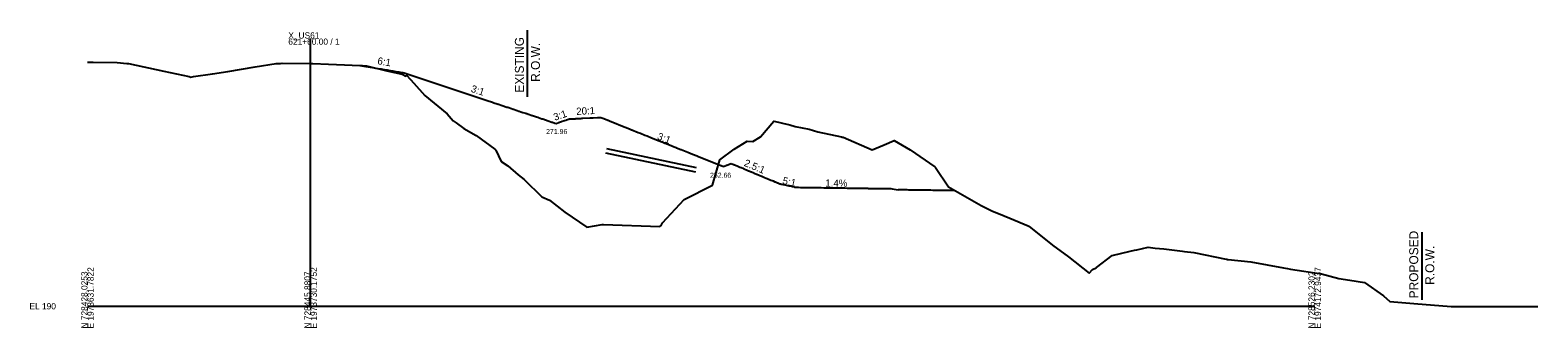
# Model space of a CAD drawing. Extents: x -26 to 1629, y -25 to 9635.
# Drawn here: x -26 to 650, y 3990 to 4124 of the extents above; entities that cross this region are included whole.
import ezdxf

# ---------------------------------------------------------------- set-up
doc = ezdxf.new("R2010")
doc.units = 0
for name, color, linetype in [('Default', 7, 'Continuous'), ('Draft_XS_Grid', 7, 'Continuous'), ('DTM CONTOURS_MAJOR', 7, 'Continuous'), ('DTM_X_GROUND', 7, 'Continuous'), ('XS_CELL', 7, 'Continuous'), ('XS_P_DRAINAGE', 7, 'Continuous'), ('XS_P_GROUND', 7, 'Continuous'), ('XS_P_ROW', 7, 'Continuous'), ('XS_P_TX_DCH', 7, 'Continuous'), ('XS_P_TX_FS_BS', 7, 'Continuous'), ('XS_X_ROW', 7, 'Continuous')]:
    doc.layers.add(name, color=color, linetype=linetype)

msp = doc.modelspace()

# ---------------------------------------------------------------- linework, layer by layer
at = {"layer": 'DTM_X_GROUND'}
msp.add_lwpolyline([(0, 4109.46), (2.62, 4109.41), (13.29, 4109.19), (17.62, 4108.81), (18.34, 4108.75), (34.25, 4105.36), (45.61, 4102.95), (46.39, 4102.76), (47.51, 4102.94), (56.02, 4104.25), (62.92, 4105.3), (75.1, 4107.28), (84.49, 4108.78), (86.52, 4108.86), (87.19, 4108.89), (99.89, 4108.85), (100.95, 4108.84), (108.01, 4108.54), (115.16, 4108.24), (122.13, 4107.95), (123.25, 4107.86), (125.02, 4107.71), (134.18, 4105.55), (141.02, 4103.98), (142.73, 4103.15), (143.07, 4103.49), (146.27, 4100.06), (151.17, 4094.5), (161.13, 4086.23), (163.95, 4083.12), (165.26, 4082.2), (168.72, 4079.69), (174.17, 4076.57), (182.55, 4070.44), (183.05, 4070.01), (185.37, 4064.86), (188.35, 4062.95), (193.06, 4058.86), (195.69, 4056.78), (203.58, 4048.99), (207, 4047.56), (213.96, 4042.24), (223.75, 4035.43), (230.61, 4036.58), (231.17, 4036.66), (231.29, 4036.64), (256.44, 4035.81), (257.08, 4036.15), (257.66, 4037.39), (267.43, 4047.85), (280.06, 4054.29), (283.33, 4065.69), (289.85, 4070.43), (295.59, 4073.96), (298.17, 4073.78), (301.65, 4075.89), (307.58, 4082.92), (309.64, 4082.44), (311.48, 4082.03), (314.83, 4081.26), (317.1, 4080.63), (323.4, 4079.33), (327.36, 4078.21), (337.86, 4076.01), (338.26, 4075.86), (338.47, 4075.79), (338.64, 4075.73), (351.69, 4070.11), (357.03, 4072.36), (361.46, 4074.24), (368.65, 4070.07), (379.82, 4062.47), (380.09, 4062.15), (385.81, 4053.5), (400.47, 4045.14), (403.76, 4043.54), (405.25, 4042.82), (410.88, 4040.5), (413.31, 4039.49), (421.54, 4036.02), (421.71, 4035.95), (421.85, 4035.85), (432.43, 4027.37), (439.61, 4022.07), (448.85, 4014.81), (450.42, 4016.41), (451.99, 4017.28), (452.19, 4017.36), (459.28, 4022.76), (467.33, 4024.62), (469.18, 4025.16), (470.33, 4025.29), (475.33, 4026.47), (478.49, 4026.04), (482.41, 4025.67), (490.78, 4024.72), (491.65, 4024.6), (495.86, 4024.04), (510.33, 4021.08), (510.68, 4021.03), (510.91, 4020.99), (511.25, 4020.94), (521.4, 4019.95), (536.06, 4017.2), (537.8, 4016.95), (539.17, 4016.68), (553, 4014.59), (560.79, 4012.36), (565.77, 4011.69), (572.25, 4010.63), (580.88, 4004.6), (583.61, 4002.06), (596.27, 4001.12), (609.32, 4000), (611.14, 3999.89), (612.47, 3999.89), (614.22, 3999.88), (630.74, 3999.85), (638.79, 3999.94), (650, 3999.93)], dxfattribs=at)
at = {"layer": 'XS_CELL'}
for p, q in [((100, 4000), (100, 4120)), ((0, 4000), (100, 4000)), ((100, 4000), (550, 4000))]:
    msp.add_line(p, q, dxfattribs=at)
at = {"layer": 'XS_P_DRAINAGE'}
for p, q in [((232.15, 4068.7), (272.44, 4060.26)), ((232.56, 4070.65), (272.85, 4062.22))]:
    msp.add_line(p, q, dxfattribs=at)
at = {"layer": 'XS_P_GROUND'}
for points in [[(122, 4107.96), (124.77, 4107.49), (127.71, 4107), (129.02, 4106.79), (130.33, 4106.57), (131.65, 4106.35), (132.96, 4106.13), (134.27, 4105.91), (135.58, 4105.69), (136.89, 4105.47), (138.21, 4105.26), (139.52, 4105.04), (140.17, 4104.93), (140.69, 4104.84), (141.37, 4104.73), (142, 4104.62)], [(142, 4104.62), (145.03, 4103.61), (145.13, 4103.58), (178.74, 4092.38), (179.55, 4092.11), (179.56, 4092.1), (179.97, 4091.97), (180.01, 4091.95), (181.62, 4091.42), (181.68, 4091.4), (184.11, 4090.59), (184.15, 4090.57), (185.78, 4090.03), (185.84, 4090.01), (187.98, 4089.3), (187.99, 4089.29), (188.3, 4089.19), (188.34, 4089.18), (189.99, 4088.63), (190.01, 4088.62), (190.84, 4088.34), (190.88, 4088.33), (192.54, 4087.78), (192.56, 4087.77), (193.39, 4087.49), (193.41, 4087.49), (194.25, 4087.21), (194.27, 4087.2), (195.1, 4086.92), (195.14, 4086.91), (196.4, 4086.49), (196.52, 4086.45), (196.83, 4086.35), (197.42, 4086.15), (197.7, 4086.06), (199.25, 4085.54), (199.45, 4085.47), (199.93, 4085.31), (200.8, 4085.02), (200.82, 4085.02), (200.82, 4085.02), (201.21, 4084.89), (201.83, 4084.68), (202.09, 4084.59), (203.66, 4084.07), (203.85, 4084), (203.96, 4083.97), (204, 4083.96), (206.52, 4083.12), (206.52, 4083.12), (206.52, 4083.12), (208.14, 4082.57), (208.29, 4082.52), (208.31, 4082.52), (208.39, 4082.49), (209.51, 4082.12), (210, 4081.96), (210.82, 4082.23), (211.01, 4082.29), (211.34, 4082.4), (211.54, 4082.47), (212.45, 4082.77), (212.57, 4082.81), (212.81, 4082.89), (213.79, 4083.22), (214.48, 4083.45), (214.63, 4083.5), (214.64, 4083.5), (215.59, 4083.82), (215.68, 4083.85), (216, 4083.96), (216.34, 4083.97), (216.45, 4083.98), (217.2, 4084.02), (217.37, 4084.02), (218.55, 4084.08), (218.85, 4084.1), (219.84, 4084.15), (219.92, 4084.15), (220.85, 4084.2), (221, 4084.21), (221.05, 4084.21), (221.17, 4084.21), (221.59, 4084.24), (221.89, 4084.25), (221.98, 4084.26), (225.12, 4084.41), (225.7, 4084.44), (226.6, 4084.49), (226.64, 4084.49), (226.68, 4084.49), (228.52, 4084.58), (228.54, 4084.58), (229.46, 4084.63), (229.52, 4084.63), (230, 4084.66), (231.35, 4084.12), (231.4, 4084.1), (233.25, 4083.35), (233.28, 4083.35), (234.21, 4082.97), (234.25, 4082.95), (236.12, 4082.21), (236.19, 4082.18), (239.01, 4081.05), (239.06, 4081.03), (240.95, 4080.28), (240.99, 4080.26), (242.89, 4079.5), (242.92, 4079.49), (243.87, 4079.11), (243.94, 4079.08), (246.81, 4077.93), (246.83, 4077.92), (247.8, 4077.54), (247.84, 4077.52), (249.77, 4076.75), (249.8, 4076.74), (250.77, 4076.35), (250.81, 4076.33), (252.76, 4075.55), (252.81, 4075.53), (254.76, 4074.75), (254.78, 4074.74), (255.76, 4074.35), (255.81, 4074.33), (257.78, 4073.55), (257.8, 4073.54), (258.79, 4073.14), (258.84, 4073.12), (260.82, 4072.33), (260.87, 4072.31), (262.86, 4071.51), (262.88, 4071.5), (263.88, 4071.1), (263.93, 4071.08), (265.94, 4070.28), (266.01, 4070.25), (269.04, 4069.04), (269.09, 4069.02), (271.12, 4068.21), (271.17, 4068.19), (273.21, 4067.37), (273.4, 4067.29), (279, 4065.06), (279.06, 4065.03), (283.79, 4063.14), (283.92, 4063.09), (285, 4062.66), (285.17, 4062.72), (285.41, 4062.82), (285.86, 4063), (285.94, 4063.03), (286.08, 4063.09), (286.11, 4063.1), (286.44, 4063.23), (286.48, 4063.25), (288.41, 4064.02)], [(288.41, 4064.02), (289.49, 4063.57), (289.73, 4063.47), (290.65, 4063.09), (291.09, 4062.91), (291.8, 4062.61), (292.4, 4062.36), (292.96, 4062.12), (293.69, 4061.82), (294.12, 4061.64), (294.95, 4061.29), (295.28, 4061.16), (296.2, 4060.77), (296.43, 4060.67), (297.42, 4060.26), (297.59, 4060.19), (298.64, 4059.75), (298.75, 4059.71), (299.86, 4059.24), (299.91, 4059.22), (301.01, 4058.76), (301.06, 4058.74), (301.06, 4058.74), (302.1, 4058.31), (302.22, 4058.26), (303.13, 4057.88), (303.38, 4057.77), (304.17, 4057.44), (304.54, 4057.29), (305.21, 4057.01), (305.7, 4056.81), (306.24, 4056.58), (306.85, 4056.32), (307.28, 4056.15), (308.01, 4055.84), (308.32, 4055.71), (309.17, 4055.36), (309.35, 4055.28), (310.33, 4054.87), (310.39, 4054.85), (310.94, 4054.62)], [(316.89, 4053.33), (316.11, 4053.5), (315.93, 4053.54), (314.96, 4053.75), (314.49, 4053.85), (313.8, 4054), (313.33, 4054.1), (312.64, 4054.25), (311.62, 4054.47), (311.48, 4054.5), (310.94, 4054.62)], [(316.89, 4053.33), (317.27, 4053.33), (317.32, 4053.33), (318.43, 4053.31), (318.63, 4053.31), (319.59, 4053.29), (319.94, 4053.29), (320.74, 4053.28), (321.25, 4053.27), (321.9, 4053.26), (322.56, 4053.25), (323.06, 4053.24), (323.87, 4053.23), (324.22, 4053.23), (325.18, 4053.21), (325.37, 4053.21), (326.49, 4053.19), (326.53, 4053.19), (326.82, 4053.19), (327.69, 4053.18), (327.7, 4053.18), (328.85, 4053.16), (328.88, 4053.16), (330.01, 4053.14), (330.06, 4053.14), (331.16, 4053.13), (331.23, 4053.13), (332.32, 4053.11), (332.41, 4053.11), (333.48, 4053.09), (333.59, 4053.09), (334.64, 4053.08), (334.76, 4053.08), (335.79, 4053.06), (335.94, 4053.06), (336.95, 4053.04), (337.12, 4053.04), (338.11, 4053.03), (338.29, 4053.02), (339.27, 4053.01), (339.47, 4053.01), (340.42, 4052.99), (340.65, 4052.99), (341.58, 4052.98), (341.83, 4052.97), (342.74, 4052.96), (343, 4052.96), (343.9, 4052.94), (344.18, 4052.94), (345.05, 4052.93), (345.36, 4052.92), (346.21, 4052.91), (346.54, 4052.9), (347.37, 4052.89), (347.72, 4052.89), (348.53, 4052.88), (348.9, 4052.87), (349.68, 4052.86), (350.08, 4052.85), (350.84, 4052.84), (351.26, 4052.84), (352, 4052.83), (352.44, 4052.82), (353.16, 4052.81), (353.62, 4052.8), (354.31, 4052.79), (354.8, 4052.79), (355.47, 4052.78), (355.98, 4052.77), (356.63, 4052.76), (357.16, 4052.75), (357.79, 4052.74), (358.34, 4052.73), (358.95, 4052.73), (359.52, 4052.72), (360.1, 4052.71), (360.7, 4052.7), (363.28, 4052.17), (363.28, 4052.17), (363.28, 4052.17), (363.28, 4052.17), (363.28, 4052.17)], [(388.79, 4051.8), (388.17, 4051.81), (388.16, 4051.81), (387.01, 4051.83), (386.98, 4051.83), (385.86, 4051.84), (385.79, 4051.85), (384.7, 4051.86), (384.57, 4051.86), (383.54, 4051.88), (383.35, 4051.88), (382.38, 4051.89), (382.18, 4051.9), (381.22, 4051.91), (381, 4051.91), (380.07, 4051.93), (379.16, 4051.94), (378.91, 4051.95), (378.02, 4051.96), (377.75, 4051.96), (376.87, 4051.97), (376.59, 4051.98), (375.73, 4051.99), (375.44, 4052), (374.59, 4052.01), (374.28, 4052.01), (373.45, 4052.02), (373.12, 4052.03), (372.31, 4052.04), (371.96, 4052.05), (371.16, 4052.06), (370.81, 4052.06), (370.44, 4052.07), (369.65, 4052.08), (369.26, 4052.08), (368.49, 4052.1), (368.07, 4052.1), (367.33, 4052.11), (366.89, 4052.12), (366.18, 4052.13), (365.71, 4052.14), (365.02, 4052.15), (364.53, 4052.15), (363.86, 4052.16), (363.61, 4052.17), (363.28, 4052.17), (363.28, 4052.17), (363.27, 4052.17)]]:
    msp.add_lwpolyline(points, dxfattribs=at)
at = {"layer": 'XS_P_ROW'}
msp.add_line((598, 4033.2), (598, 4002.88), dxfattribs=at)
at = {"layer": 'XS_X_ROW'}
msp.add_line((197, 4123.76), (197, 4093.87), dxfattribs=at)

# ---------------------------------------------------------------- texts
at = {"layer": 'Default'}
for p in [(141.96, 4104.56), (316.85, 4053.27)]:
    msp.add_text('X', height=0.12, dxfattribs=at).set_placement(p)
at = {"layer": 'Draft_XS_Grid'}
msp.add_text('-', height=0.0001, dxfattribs=at).set_placement((0, 4000))
at = {"layer": 'DTM CONTOURS_MAJOR'}
for p in [(121.96, 4107.9), (141.96, 4104.56), (203.96, 4083.9), (209.96, 4081.9), (215.96, 4083.9), (229.96, 4084.6), (278.96, 4065), (284.96, 4062.6), (284.96, 4061.6), (290.96, 4065), (300.97, 4064.1), (300.97, 4064.1), (300.97, 4058.7), (310.9, 4054.56), (310.9, 4054.56), (326.78, 4053.13)]:
    msp.add_text('X', height=0.12, dxfattribs=at).set_placement(p)
at = {"layer": 'XS_CELL'}
for s, p in [('X_US61', (90, 4120)), ('621+60.00 / 1', (90, 4117.2)), ('EL 190', (-26, 3998.6))]:
    msp.add_text(s, height=2.8, dxfattribs=at).set_placement(p)
for s, p in [('N 728428.0253', (0, 3990)), ('E 1973631.7822', (2.8, 3990)), ('N 728445.8807', (100, 3990)), ('E 1973730.1752', (102.8, 3990)), ('N 728526.2302', (550, 3990)), ('E 1974172.9437', (552.8, 3990))]:
    msp.add_text(s, height=2.8, rotation=90, dxfattribs=at).set_placement(p)
at = {"layer": 'XS_P_ROW'}
for s, p in [('PROPOSED', (596.37, 4003.52)), ('R.O.W.', (603.57, 4009.59))]:
    msp.add_text(s, height=4, rotation=90, dxfattribs=at).set_placement(p)
at = {"layer": 'XS_P_TX_DCH'}
for s, p in [('271.96', (205.54, 4077.19)), ('252.66', (279.01, 4057.6))]:
    msp.add_text(s, height=2.25, dxfattribs=at).set_placement(p)
at = {"layer": 'XS_P_TX_FS_BS'}
for s, rotation, p in [('6:1', 350.53766, (129.77, 4108.51)), ('3:1', 341.56507, (171.57, 4096.2)), ('20:1', 2.86241, (219.12, 4085.75)), ('3:1', 18.43493, (209.43, 4083.1)), ('3:1', 338.19859, (255.05, 4074.96)), ('2.5:1', 337.34141, (293.96, 4063.03)), ('5:1', 347.81336, (311.28, 4054.85)), ('1.4%', 359.17115, (330.66, 4053.63))]:
    msp.add_text(s, height=3.24, rotation=rotation, dxfattribs=at).set_placement(p)
at = {"layer": 'XS_X_ROW'}
for s, p in [('EXISTING', (195.56, 4095.73)), ('R.O.W.', (202.76, 4100.57))]:
    msp.add_text(s, height=4, rotation=90, dxfattribs=at).set_placement(p)

doc.saveas('drawing.dxf')
